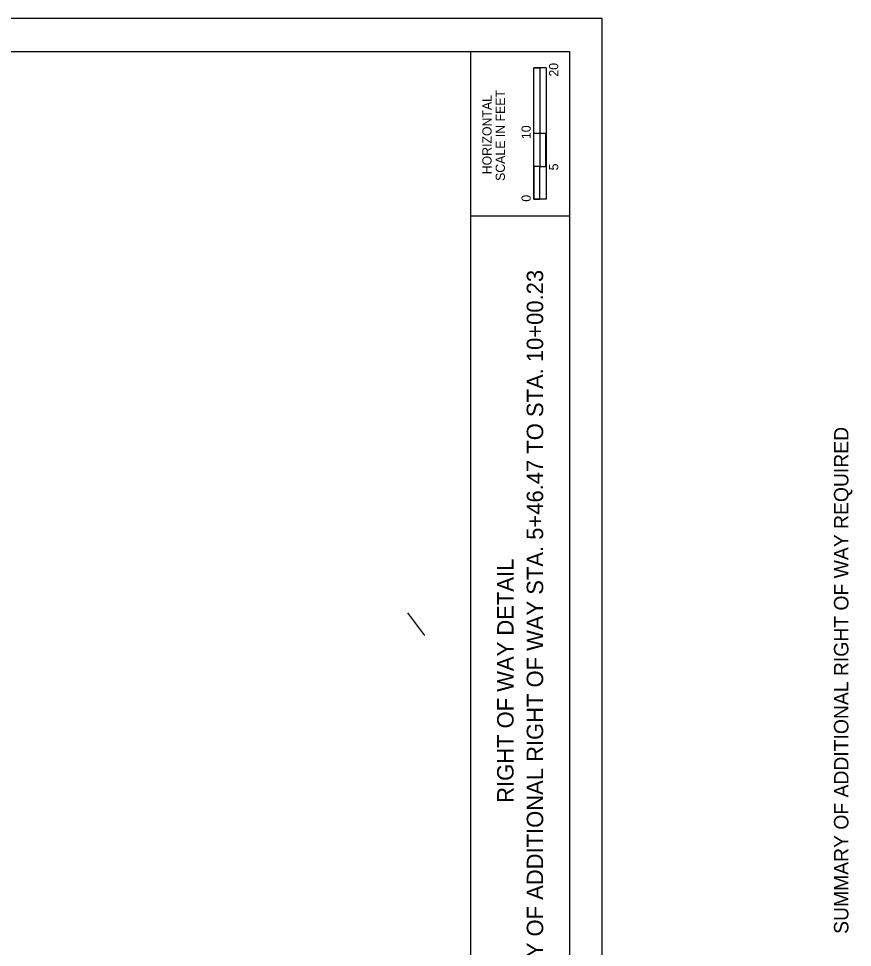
# Model space of a CAD drawing. Extents: x 54.5 to 92.3, y 4.7 to 26.7.
# Drawn here: x 79.64 to 92.33, y 12.58 to 26.72 of the extents above; entities that cross this region are included whole.
import ezdxf

# ---------------------------------------------------------------- set-up
doc = ezdxf.new("R2010")
doc.units = 0
for name, color, linetype in [('SH_Border', 7, 'Continuous'), ('SH_Cut_Line', 7, 'Continuous'), ('SH_Data', 7, 'Continuous'), ('SH_Text', 7, 'Continuous'), ('TX_P_10', 7, 'Continuous')]:
    doc.layers.add(name, color=color, linetype=linetype)

msp = doc.modelspace()

# ---------------------------------------------------------------- linework, layer by layer
at = {"layer": 'SH_Border'}
for p, q in [((86.523, 5.217), (86.523, 26.217)), ((86.523, 23.717), (88.023, 23.717))]:
    msp.add_line(p, q, dxfattribs=at)
msp.add_lwpolyline([(56.023, 26.217), (88.023, 26.217), (88.023, 5.217), (56.023, 5.217)], close=True, dxfattribs=at)
at = {"layer": 'SH_Cut_Line'}
msp.add_lwpolyline([(54.523, 4.717), (88.523, 4.717), (88.523, 26.717), (54.523, 26.717)], close=True, dxfattribs=at)
at = {"layer": 'SH_Data'}
for p, q in [((87.48, 23.967), (87.48, 25.967)), ((87.667, 25.967), (87.48, 25.967)), ((87.48, 24.967), (87.48, 25.967)), ((87.48, 25.967), (87.573, 25.967)), ((87.573, 25.967), (87.574, 25.967)), ((87.574, 25.967), (87.574, 24.967)), ((87.667, 25.967), (87.667, 23.967)), ((87.574, 24.967), (87.48, 24.967)), ((87.666, 24.967), (87.573, 24.967)), ((87.573, 24.967), (87.573, 24.467)), ((87.666, 24.467), (87.666, 24.967)), ((87.573, 24.467), (87.48, 24.467)), ((87.48, 24.467), (87.48, 23.967)), ((87.573, 23.967), (87.573, 24.467)), ((87.573, 24.467), (87.666, 24.467)), ((87.667, 23.967), (87.48, 23.967)), ((87.48, 23.967), (87.573, 23.967))]:
    msp.add_line(p, q, dxfattribs=at)
at = {"layer": 'TX_P_10'}
msp.add_line((85.561, 17.675), (85.819, 17.329), dxfattribs=at)

# ---------------------------------------------------------------- texts
at = {"layer": 'SH_Data'}
for s, height, p in [('20', 0.14, (87.853, 25.833)), ('SCALE IN FEET', 0.14, (87.041, 24.246)), ('HORIZONTAL', 0.14, (86.838, 24.347)), ('10', 0.14, (87.434, 24.883)), ('5', 0.14, (87.853, 24.407)), ('0', 0.14, (87.434, 23.93)), ('AND SUMMARY OF ADDITIONAL RIGHT OF WAY STA. 5+46.47 TO STA. 10+00.23', 0.25, (87.623, 10.148)), ('RIGHT OF WAY DETAIL', 0.25, (87.173, 14.782))]:
    msp.add_text(s, height=height, rotation=90, dxfattribs=at).set_placement(p)
at = {"layer": 'SH_Text'}
msp.add_text('SUMMARY OF ADDITIONAL RIGHT OF WAY REQUIRED', height=0.22, rotation=90, dxfattribs=at).set_placement((92.268, 12.788))

doc.saveas('drawing.dxf')
